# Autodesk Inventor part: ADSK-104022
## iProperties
Shininess: 0.0
Created: 2001-01
Part Number: ADSK-104022
Document SubType Name: Modeling
Stock Number: ADSK-104022
Density: 1 g/cm^3
Density: 0.0
Volumn: 0.0
Area: 0.0
PropertySet Name: Model Information
Control State: 0
Master: False
Checked Out: False
Author: gao
